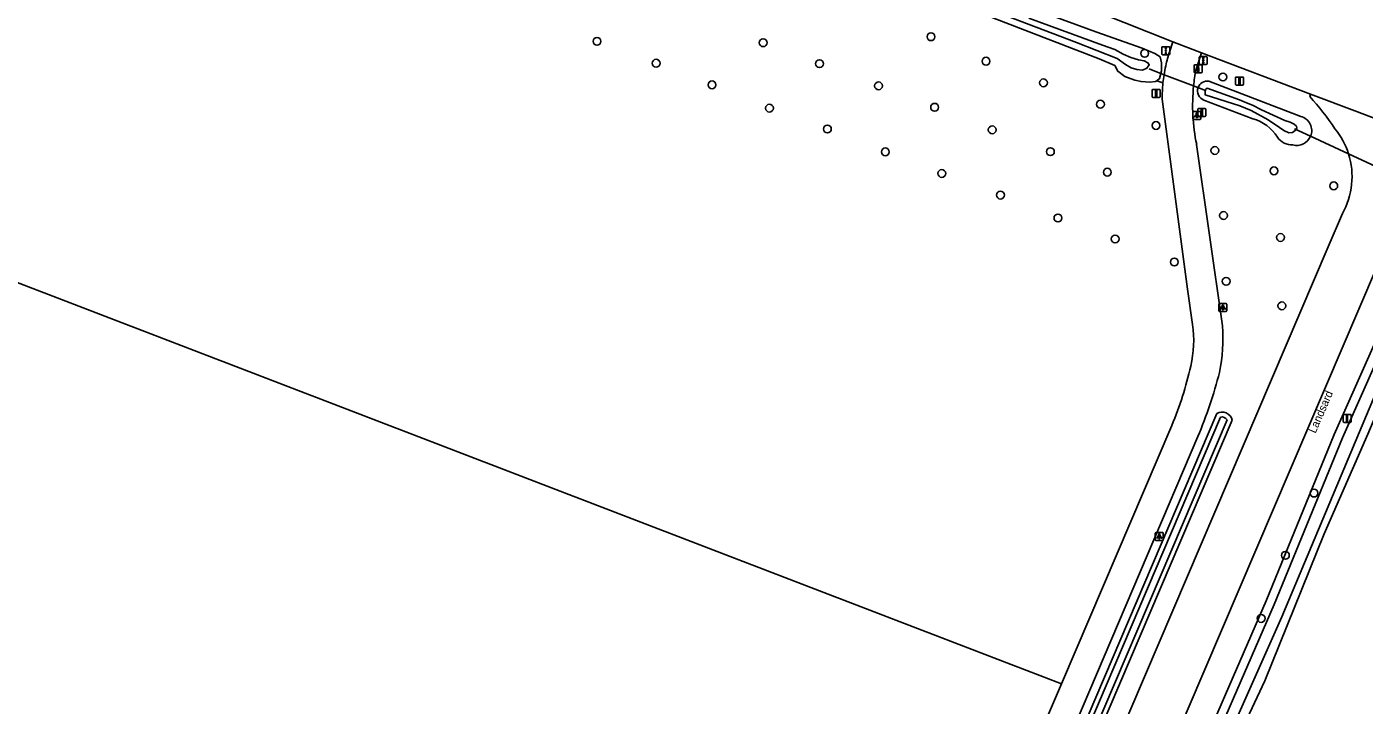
# Model space of a CAD drawing. Extents: x 155209 to 156823, y 385356 to 388482.
# Drawn here: x 155996.3 to 156163.4, y 386487.5 to 386572.2 of the extents above; entities that cross this region are included whole.
import ezdxf

# ---------------------------------------------------------------- set-up
doc = ezdxf.new("R2010")
doc.units = 0
for name, color, linetype in [('IMGEO_Boom', 7, 'Continuous'), ('IMGEO_Bouwland', 7, 'Continuous'), ('IMGEO_Drukknoppaal', 7, 'Continuous'), ('IMGEO_Duiker', 7, 'Continuous'), ('IMGEO_Fietspad_gesloten', 7, 'Continuous'), ('IMGEO_Gemengd_bos', 7, 'Continuous'), ('IMGEO_Groenvoorziening', 7, 'Continuous'), ('IMGEO_Lichtpunt', 7, 'Continuous'), ('IMGEO_Openbare_ruimte_label', 7, 'Continuous'), ('IMGEO_Portaal', 7, 'Continuous'), ('IMGEO_Rijbaan_lokaal_gesloten', 7, 'Continuous'), ('IMGEO_Verkeersbordpaal', 7, 'Continuous'), ('IMGEO_Verkeersregelinstallatiepaal', 7, 'Continuous'), ('IMGEO_Waterloop', 7, 'Continuous')]:
    doc.layers.add(name, color=color, linetype=linetype)

msp = doc.modelspace()

# ---------------------------------------------------------------- linework, layer by layer
at = {"layer": 'IMGEO_Boom'}
for centre in [(156109.23, 386570.96), (156067.5, 386570.39), (156088.26, 386570.21), (156135.92, 386568.88), (156074.89, 386567.65), (156095.3, 386567.59), (156116.11, 386567.9), (156145.7, 386565.93), (156081.87, 386564.95), (156102.68, 386564.83), (156123.28, 386565.21), (156109.68, 386562.15), (156130.4, 386562.53), (156089.05, 386562.04), (156096.29, 386559.43), (156116.88, 386559.33), (156137.35, 386559.87), (156103.53, 386556.58), (156124.15, 386556.6), (156144.7, 386556.75), (156110.58, 386553.88), (156131.27, 386554.04), (156152.08, 386554.21), (156159.55, 386552.33), (156117.91, 386551.18), (156125.09, 386548.32), (156145.78, 386548.63), (156132.24, 386545.7), (156152.9, 386545.89), (156139.63, 386542.82), (156146.11, 386540.41), (156153.07, 386537.35), (156157.08, 386513.96), (156153.51, 386506.18), (156150.48, 386498.3)]:
    msp.add_circle(centre, 0.489, dxfattribs=at)
at = {"layer": 'IMGEO_Bouwland'}
for points in [[(156040.24, 386604.88), (156039.24, 386604.81), (156038.99, 386604.12), (156039.21, 386603.34), (156045.7, 386600.84), (156130.25, 386568.22), (156132.19, 386567.35), (156132.58, 386566.64), (156133.44, 386566), (156134.71, 386565.54), (156135.48, 386565.36), (156136.57, 386565.29), (156137.3, 386565.35), (156137.44, 386565.47)], [(156138.21, 386565.19), (156137.44, 386565.47)], [(155948.54, 386558.13), (156125.52, 386490.13)]]:
    msp.add_lwpolyline(points, dxfattribs=at)
at = {"layer": 'IMGEO_Drukknoppaal'}
for p, q in [((156142.11, 386566.57), (156142.11, 386567.37)), ((156142.11, 386567.37), (156142.11, 386566.57)), ((156142.21, 386567.47), (156143, 386567.47)), ((156143, 386567.47), (156142.21, 386567.47)), ((156143, 386566.47), (156142.21, 386566.47)), ((156142.21, 386566.47), (156143, 386566.47)), ((156143.1, 386567.37), (156143.1, 386566.57)), ((156143.1, 386566.57), (156143.1, 386567.37))]:
    msp.add_line(p, q, dxfattribs=at)
msp.add_lwpolyline([(156142.68, 386567.1), (156142.68, 386566.6), (156142.53, 386566.6), (156142.53, 386567.1), (156142.68, 386567.1)], dxfattribs=at)
msp.add_circle((156142.6, 386567.26), 0.085, dxfattribs=at)
for centre, start, end in [((156142.21, 386567.37), 90, 180), ((156142.21, 386567.37), 90, 180), ((156142.21, 386566.57), 180, 270), ((156142.21, 386566.57), 180, 270), ((156143, 386567.37), 0, 90), ((156143, 386567.37), 360, 90), ((156143, 386566.57), 270, 0), ((156143, 386566.57), 270, 0)]:
    msp.add_arc(centre, 0.1, start, end, dxfattribs=at)
at = {"layer": 'IMGEO_Duiker'}
for points in [[(156143.51, 386564.26), (156142.59, 386564.6), (156142.04, 386564.81), (156138.35, 386566.2), (156137.4, 386566.58), (156136.47, 386566.95)], [(156154.66, 386559.47), (156156.66, 386558.54), (156161.4, 386556.33), (156168.13, 386553.2), (156173, 386550.94), (156177.24, 386548.97)]]:
    msp.add_lwpolyline(points, dxfattribs=at)
at = {"layer": 'IMGEO_Fietspad_gesloten'}
for points in [[(156139.46, 386570.31), (156139.07, 386569.16)], [(156143.03, 386568.96), (156142.35, 386566.9)], [(156141.9, 386535.02), (156141.28, 386539.44), (156138.11, 386563.18)], [(156142.42, 386557.48), (156145.65, 386534.83)], [(156142.59, 386521.01), (156114.61, 386455.4), (156091.23, 386400.62), (156069.84, 386350.23), (156058.06, 386322.41), (156046.41, 386294.89), (156023.01, 386239.56), (156010, 386208.82), (156005, 386197.04)], [(156125.52, 386490.13), (156139.32, 386522.4)], [(156125.52, 386490.13), (156111.26, 386456.76), (156087.98, 386402.17), (156066.59, 386351.85), (156054.72, 386323.81), (156054.54, 386323.39)]]:
    msp.add_lwpolyline(points, dxfattribs=at)
for centre, radius, start, end in [((156156.95, 386563.24), 18.84, 161.6813, 167.4703), ((156156.54, 386563.27), 18.43, 170.87, 174.0446), ((156156.73, 386563.29), 18.61, 167.4723, 171.0196), ((156166.66, 386562.21), 24.76, 169.0787, 171.619), ((156157.41, 386563.18), 19.3, 174.0499, 180.0174), ((156165.76, 386562.37), 23.84, 174.1168, 191.8202), ((156163.24, 386562.68), 21.31, 171.5205, 174.2574), ((156128.03, 386532.99), 14.02, 346.9203, 8.3243), ((156124.45, 386533.26), 21.26, 348.5374, 4.2373), ((156099.77, 386539.08), 42.92, 337.1382, 347.5424), ((156082.04, 386545.84), 65.44, 337.7022, 345.1198)]:
    msp.add_arc(centre, radius, start, end, dxfattribs=at)
at = {"layer": 'IMGEO_Gemengd_bos'}
msp.add_lwpolyline([(156070.14, 386302.11), (156080.46, 386328.34), (156096.12, 386365.96), (156141.39, 386470.18), (156150.93, 386490.49), (156158.36, 386508.88), (156163.81, 386521.3), (156167.26, 386529.54), (156172.79, 386541.9), (156173.42, 386543.01), (156176.13, 386545.72), (156177.73, 386546.35)], dxfattribs=at)
at = {"layer": 'IMGEO_Groenvoorziening'}
for points in [[(156137.44, 386565.47), (156137.76, 386565.73), (156138.02, 386566.69), (156138.04, 386567.52), (156138.05, 386567.68), (156137.88, 386568.44), (156137.2, 386568.86), (156135.61, 386569.52), (156129.81, 386571.56), (156123.14, 386574.02), (156096.99, 386583.72), (156080.99, 386589.91), (156046.53, 386602.9), (156040.24, 386604.88)], [(156155.43, 386561), (156143.94, 386565.39)], [(156143.34, 386563.05), (156149.43, 386560.71)], [(156063.56, 386292.58), (156064.47, 386293.87), (156065.2, 386295.28), (156082.6, 386339.09), (156140.39, 386475.84), (156151.1, 386500.48), (156159.62, 386521.29), (156166.27, 386536.26), (156169.74, 386543.04), (156171.1, 386545.31), (156172.2, 386546.57), (156173.2, 386547.64)], [(156144.95, 386523.89), (156070.68, 386349.65), (156026.29, 386245.49)], [(156028.61, 386244.59), (156072.67, 386349.22), (156146.86, 386523.08)]]:
    msp.add_lwpolyline(points, dxfattribs=at)
for centre, radius, start, end in [((156143.72, 386564.19), 1.2, 159.8971, 251.4762), ((156143.73, 386564.2), 1.21, 80.1681, 160.3977), ((156154.95, 386559.22), 1.85, 338.1768, 74.7301), ((156148.05, 386555.67), 5.23, 31.609, 74.681), ((156154.4, 386559.79), 2.35, 216.1722, 271.2872), ((156154.93, 386559.25), 1.87, 255.1017, 337.5493), ((156145.61, 386522.78), 1.29, 13.4771, 120.5825)]:
    msp.add_arc(centre, radius, start, end, dxfattribs=at)
at = {"layer": 'IMGEO_Lichtpunt'}
for p, q in [((156141.95, 386561.55), (156141.95, 386560.74)), ((156141.95, 386561.55), (156141.95, 386560.74)), ((156142.85, 386561.64), (156142.05, 386561.64)), ((156142.85, 386561.64), (156142.05, 386561.64)), ((156142.95, 386560.74), (156142.95, 386561.55)), ((156142.95, 386560.74), (156142.95, 386561.55)), ((156142.05, 386560.64), (156142.85, 386560.64)), ((156142.05, 386560.64), (156142.85, 386560.64)), ((156145.2, 386537.54), (156145.2, 386536.74)), ((156145.2, 386537.54), (156145.2, 386536.74)), ((156146.1, 386537.64), (156145.3, 386537.64)), ((156146.1, 386537.64), (156145.3, 386537.64)), ((156146.2, 386536.74), (156146.2, 386537.54)), ((156146.2, 386536.74), (156146.2, 386537.54)), ((156145.3, 386536.64), (156146.1, 386536.64)), ((156145.3, 386536.64), (156146.1, 386536.64)), ((156137.26, 386508.94), (156137.26, 386508.13)), ((156137.26, 386508.94), (156137.26, 386508.13)), ((156138.16, 386509.03), (156137.35, 386509.03)), ((156138.16, 386509.03), (156137.35, 386509.03)), ((156137.35, 386508.04), (156138.16, 386508.04)), ((156137.35, 386508.04), (156138.16, 386508.04)), ((156138.25, 386508.13), (156138.25, 386508.94)), ((156138.25, 386508.13), (156138.25, 386508.94))]:
    msp.add_line(p, q, dxfattribs=at)
for points in [[(156142.33, 386561.21), (156142.36, 386561.18), (156142.18, 386560.92), (156142.14, 386560.95), (156142.33, 386561.21)], [(156142.43, 386561.16), (156142.48, 386561.16), (156142.48, 386560.84), (156142.43, 386560.84), (156142.43, 386561.16)], [(156142.54, 386561.18), (156142.58, 386561.21), (156142.76, 386560.95), (156142.72, 386560.92), (156142.54, 386561.18)], [(156145.58, 386537.21), (156145.62, 386537.18), (156145.43, 386536.92), (156145.39, 386536.94), (156145.58, 386537.21)], [(156145.68, 386537.16), (156145.73, 386537.16), (156145.73, 386536.84), (156145.68, 386536.84), (156145.68, 386537.16)], [(156145.79, 386537.18), (156145.83, 386537.21), (156146.01, 386536.94), (156145.98, 386536.92), (156145.79, 386537.18)], [(156137.63, 386508.6), (156137.67, 386508.57), (156137.48, 386508.31), (156137.44, 386508.34), (156137.63, 386508.6)], [(156137.73, 386508.55), (156137.78, 386508.55), (156137.78, 386508.23), (156137.73, 386508.23), (156137.73, 386508.55)], [(156137.84, 386508.57), (156137.88, 386508.6), (156138.07, 386508.34), (156138.03, 386508.31), (156137.84, 386508.57)]]:
    msp.add_lwpolyline(points, dxfattribs=at)
for centre in [(156142.45, 386561.34), (156145.7, 386537.34), (156137.76, 386508.74)]:
    msp.add_circle(centre, 0.0994, dxfattribs=at)
for centre, start, end in [((156142.05, 386561.55), 90, 180), ((156142.05, 386561.55), 90, 180), ((156142.85, 386561.55), 0, 90), ((156142.85, 386561.55), 0, 90), ((156142.05, 386560.74), 180, 270), ((156142.05, 386560.74), 180, 270), ((156142.85, 386560.74), 270, 0), ((156142.85, 386560.74), 270, 360), ((156145.3, 386537.54), 90, 180), ((156145.3, 386537.54), 90, 180), ((156146.1, 386537.54), 0, 90), ((156146.1, 386537.54), 0, 90), ((156145.3, 386536.74), 180, 270), ((156145.3, 386536.74), 180, 270), ((156146.1, 386536.74), 270, 0), ((156146.1, 386536.74), 270, 360), ((156137.35, 386508.94), 90, 180), ((156137.35, 386508.94), 90, 180), ((156137.35, 386508.13), 180, 270), ((156137.35, 386508.13), 180, 270), ((156138.16, 386508.94), 0, 90), ((156138.16, 386508.94), 0, 90), ((156138.16, 386508.13), 270, 0), ((156138.16, 386508.13), 270, 360)]:
    msp.add_arc(centre, 0.0946, start, end, dxfattribs=at)
at = {"layer": 'IMGEO_Portaal'}
for p, q in [((156147.28, 386565.03), (156147.28, 386565.83)), ((156147.28, 386565.83), (156147.28, 386565.03)), ((156147.38, 386565.93), (156148.17, 386565.93)), ((156148.17, 386565.93), (156147.38, 386565.93)), ((156148.17, 386564.93), (156147.38, 386564.93)), ((156147.38, 386564.93), (156148.17, 386564.93)), ((156148.27, 386565.83), (156148.27, 386565.03)), ((156148.27, 386565.03), (156148.27, 386565.83))]:
    msp.add_line(p, q, dxfattribs=at)
msp.add_lwpolyline([(156147.7, 386565.8), (156147.85, 386565.8), (156147.85, 386565.05), (156147.7, 386565.05), (156147.7, 386565.8)], dxfattribs=at)
for centre, start, end in [((156147.38, 386565.83), 90, 180), ((156147.38, 386565.83), 90, 180), ((156147.38, 386565.03), 180, 270), ((156147.38, 386565.03), 180, 270), ((156148.17, 386565.83), 0, 90), ((156148.17, 386565.83), 360, 90), ((156148.17, 386565.03), 270, 0), ((156148.17, 386565.03), 270, 0)]:
    msp.add_arc(centre, 0.1, start, end, dxfattribs=at)
at = {"layer": 'IMGEO_Rijbaan_lokaal_gesloten'}
for points in [[(155879.41, 386670.4), (156000, 386623.97), (156047.62, 386605.62), (156122.66, 386576.84), (156130.33, 386573.94), (156139.46, 386570.31)], [(156139.46, 386570.31), (156143.03, 386568.96)], [(156143.03, 386568.96), (156156.66, 386563.78)], [(156156.55, 386563.49), (156156.66, 386563.78)], [(156156.66, 386563.78), (156162.51, 386561.56), (156182.05, 386554.14)], [(156010.67, 386196.17), (156028.11, 386237.4), (156051.19, 386291.96), (156074.96, 386348.06), (156088.15, 386379.28), (156100.53, 386408.28), (156128.81, 386474.42), (156158.86, 386544.7), (156160.63, 386548.86)], [(156164.88, 386542.11), (156134.86, 386471.86), (156106.55, 386405.65), (156094.2, 386376.75), (156080.93, 386345.4), (156057.35, 386289.66), (156034.16, 386234.85), (156023.57, 386209.85)]]:
    msp.add_lwpolyline(points, dxfattribs=at)
for centre, radius, start, end in [((156130.28, 386539.78), 35.39, 33.7829, 42.0577), ((156152.44, 386553.47), 9.41, 17.7403, 39.5755), ((156152.46, 386553.48), 9.38, 330.5109, 17.67)]:
    msp.add_arc(centre, radius, start, end, dxfattribs=at)
at = {"layer": 'IMGEO_Verkeersbordpaal'}
for p, q in [((156136.86, 386563.48), (156136.86, 386564.28)), ((156136.86, 386564.28), (156136.86, 386563.48)), ((156136.96, 386564.38), (156137.75, 386564.38)), ((156137.75, 386564.38), (156136.96, 386564.38)), ((156137.85, 386564.28), (156137.85, 386563.48)), ((156137.85, 386563.48), (156137.85, 386564.28)), ((156137.75, 386563.38), (156136.96, 386563.38)), ((156136.96, 386563.38), (156137.75, 386563.38)), ((156142.58, 386561.09), (156142.58, 386561.89)), ((156142.58, 386561.89), (156142.58, 386561.09)), ((156142.68, 386561.99), (156143.47, 386561.99)), ((156143.47, 386561.99), (156142.68, 386561.99)), ((156143.47, 386560.99), (156142.68, 386560.99)), ((156142.68, 386560.99), (156143.47, 386560.99)), ((156143.57, 386561.89), (156143.57, 386561.09)), ((156143.57, 386561.09), (156143.57, 386561.89)), ((156160.72, 386522.89), (156160.72, 386523.69)), ((156160.72, 386523.69), (156160.72, 386522.89)), ((156160.82, 386523.79), (156161.61, 386523.79)), ((156161.61, 386523.79), (156160.82, 386523.79)), ((156161.61, 386522.79), (156160.82, 386522.79)), ((156160.82, 386522.79), (156161.61, 386522.79)), ((156161.71, 386523.69), (156161.71, 386522.89)), ((156161.71, 386522.89), (156161.71, 386523.69))]:
    msp.add_line(p, q, dxfattribs=at)
for points in [[(156137.28, 386564.25), (156137.43, 386564.25), (156137.43, 386563.5), (156137.28, 386563.5), (156137.28, 386564.25)], [(156143, 386561.86), (156143.15, 386561.86), (156143.15, 386561.11), (156143, 386561.11), (156143, 386561.86)], [(156161.14, 386523.67), (156161.29, 386523.67), (156161.29, 386522.92), (156161.14, 386522.92), (156161.14, 386523.67)]]:
    msp.add_lwpolyline(points, dxfattribs=at)
for centre, start, end in [((156136.96, 386564.28), 90, 180), ((156136.96, 386564.28), 90, 180), ((156137.75, 386564.28), 0, 90), ((156137.75, 386564.28), 360, 90), ((156136.96, 386563.48), 180, 270), ((156136.96, 386563.48), 180, 270), ((156137.75, 386563.48), 270, 0), ((156137.75, 386563.48), 270, 0), ((156142.68, 386561.89), 90, 180), ((156142.68, 386561.89), 90, 180), ((156142.68, 386561.09), 180, 270), ((156142.68, 386561.09), 180, 270), ((156143.47, 386561.89), 0, 90), ((156143.47, 386561.89), 360, 90), ((156143.47, 386561.09), 270, 0), ((156143.47, 386561.09), 270, 0), ((156160.82, 386523.69), 90, 180), ((156160.82, 386523.69), 90, 180), ((156160.82, 386522.89), 180, 270), ((156160.82, 386522.89), 180, 270), ((156161.61, 386523.69), 0, 90), ((156161.61, 386523.69), 360, 90), ((156161.61, 386522.89), 270, 0), ((156161.61, 386522.89), 270, 0)]:
    msp.add_arc(centre, 0.1, start, end, dxfattribs=at)
at = {"layer": 'IMGEO_Verkeersregelinstallatiepaal'}
for p, q in [((156138.07, 386568.82), (156138.07, 386569.61)), ((156138.07, 386569.61), (156138.07, 386568.82)), ((156138.17, 386569.71), (156138.96, 386569.71)), ((156138.96, 386569.71), (156138.17, 386569.71)), ((156139.06, 386569.61), (156139.06, 386568.82)), ((156139.06, 386568.82), (156139.06, 386569.61)), ((156138.96, 386568.72), (156138.17, 386568.72)), ((156138.17, 386568.72), (156138.96, 386568.72)), ((156142.75, 386567.6), (156142.75, 386568.4)), ((156142.75, 386568.4), (156142.75, 386567.6)), ((156142.85, 386568.5), (156143.64, 386568.5)), ((156143.64, 386568.5), (156142.85, 386568.5)), ((156143.74, 386568.4), (156143.74, 386567.6)), ((156143.74, 386567.6), (156143.74, 386568.4)), ((156143.64, 386567.5), (156142.85, 386567.5)), ((156142.85, 386567.5), (156143.64, 386567.5))]:
    msp.add_line(p, q, dxfattribs=at)
for centre in [(156138.57, 386569.51), (156138.57, 386569.22), (156138.57, 386568.93), (156143.25, 386568.29), (156143.25, 386568), (156143.25, 386567.71)]:
    msp.add_circle(centre, 0.085, dxfattribs=at)
for centre, start, end in [((156138.17, 386569.61), 90, 180), ((156138.17, 386569.61), 90, 180), ((156138.96, 386569.61), 0, 90), ((156138.96, 386569.61), 360, 90), ((156138.17, 386568.82), 180, 270), ((156138.17, 386568.82), 180, 270), ((156138.96, 386568.82), 270, 0), ((156138.96, 386568.82), 270, 0), ((156142.85, 386568.4), 90, 180), ((156142.85, 386568.4), 90, 180), ((156143.64, 386568.4), 0, 90), ((156143.64, 386568.4), 360, 90), ((156142.85, 386567.6), 180, 270), ((156142.85, 386567.6), 180, 270), ((156143.64, 386567.6), 270, 0), ((156143.64, 386567.6), 270, 0)]:
    msp.add_arc(centre, 0.1, start, end, dxfattribs=at)
at = {"layer": 'IMGEO_Waterloop'}
for points in [[(156106.38, 386578.26), (156127.43, 386570.23), (156132.49, 386568.24), (156133.55, 386567.49), (156134.23, 386567.07), (156134.96, 386566.86), (156135.67, 386566.79), (156136.2, 386567.03), (156136.5, 386567.45), (156136.34, 386567.72), (156135.86, 386567.93), (156135.14, 386568.07), (156134.21, 386568.35), (156133.25, 386568.78), (156132.19, 386569.37), (156130.64, 386569.91), (156121.45, 386573.27)], [(156147.77, 386563.07), (156143.74, 386564.53), (156143.54, 386564.35), (156143.47, 386563.99), (156143.47, 386563.72), (156147.81, 386562.35), (156149.24, 386561.76), (156151.37, 386560.57), (156152.76, 386559.62), (156153.31, 386559.26), (156153.95, 386558.95), (156154.39, 386559.01), (156154.75, 386559.24), (156154.93, 386559.54), (156154.89, 386559.78), (156154.62, 386560.05), (156154.09, 386560.3), (156153.43, 386560.48), (156150.54, 386561.82), (156149.38, 386562.4), (156148.65, 386562.72), (156147.77, 386563.07)], [(156176.15, 386546.8), (156174.87, 386546.02), (156172.95, 386543.96), (156170.88, 386540.42), (156164.5, 386525.78), (156153.08, 386498.49), (156141.69, 386472.93), (156117.96, 386417.73), (156104.89, 386387.44)], [(156107.37, 386395.72), (156123.57, 386433.22), (156141.4, 386475.41), (156152.11, 386500.05), (156160.63, 386520.86), (156167.26, 386535.78), (156170.7, 386542.51), (156172, 386544.66), (156173.01, 386545.83), (156173.54, 386546.4), (156175.33, 386547.03)], [(156145.41, 386523.44), (156071.23, 386349.41), (156026.79, 386245.14)], [(156027.95, 386244.58), (156072.12, 386349.46), (156146.22, 386523.1)]]:
    msp.add_lwpolyline(points, dxfattribs=at)
msp.add_arc((156145.61, 386522.78), 0.693, 27.6005, 106.5491, dxfattribs=at)

# ---------------------------------------------------------------- texts
at = {"layer": 'IMGEO_Openbare_ruimte_label'}
msp.add_text('Landsard', height=1, rotation=66.5608, dxfattribs=at).set_placement((156157.27, 386521.35))

doc.saveas('drawing.dxf')
